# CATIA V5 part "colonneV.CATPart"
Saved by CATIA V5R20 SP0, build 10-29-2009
Part number: colonneV
Bounding box of the stored display mesh (mm): x -50 to 50, y -150 to 249.996, z 40 to 1049.996
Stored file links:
  D:\Dropbox\Pack 1 sylvain\mmoreau\mmoreau\mmoreau\fin\colonneV.CATPart
  U:\think motion\fin\think motion2.CATProduct
  D:\Dropbox\Pack 1 sylvain\mmoreau\mmoreau\mmoreau\fin\verinB1.CATPart
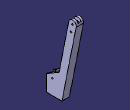
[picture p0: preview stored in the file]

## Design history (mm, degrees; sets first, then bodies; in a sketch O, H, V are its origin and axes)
External parameters (linked from other documents)
  `External.largeur levier` = 40 mm
  `External.décalage base` = 40 mm
Set1
  Line1: linked copy from another document
  Point1 to Point3: linked copy from another document
  Line2: linked copy from another document
  Point4: linked copy from another document
Body1 (main body)
  Sketch1 on yz-plane, origin (0, 0, 0), H (0, 1, 0), V (0, 0, 1)
    line L1 (249.029, 990.1942) -> (58.9902, 40)
    reference projected line E1 (200, 1000) -> (0, 0) from Line1
    line L2 (150.971, 1009.8058) -> (19.5927, 352.9144)
    line L3 (19.5927, 352.9144) -> (-150, 255)
    line L4 (58.9902, 40) -> (-150, 40)
    line L5 (-150, 255) -> (-150, 40)
    reference projected line E2 (200, 1000) -> (0, 0) from Line1
    arc A1 centre (200, 1000) radius 50 from (249.029, 990.1942) to (150.971, 1009.8058) ccw
    point P5 (200, 1000)
    reference projected point E3 (200, 1000) from Point1
    circle A2 centre (200, 1000) radius 10
    point P8 (200, 1000)
    circle A3 centre (180.3884, 901.9419) radius 10
    point P9 (180.3884, 901.9419)
    reference projected point E4 (200, 1000) from Point1
    reference projected point E5 (180.3884, 901.9419) from Point2
    distance L1 L2 = 100
    radius A2 = 10
    radius A3 = 10
    distance H L4 = 40 {= `External.décalage base`}
    angle L3 L5 = 120
    length L5 = 215
    distance L5 V = 150
    parallelism: L1 E1
    horizontal: L4 H
    vertical: L5 V
    symmetry: L1 L2 E2
    coincidence: E3 P5, P8 E4, P9 E5
    tangency: A1 L2
  Pad1: profile Sketch1, direction (1, 0, 0), length 50 {= `External.largeur levier` +10mm}, mirrored extent
  Sketch2 on yz-plane, origin (0, 0, 0), H (0, 1, 0), V (0, 0, 1)
    line L1 (261.2594, 1102.3364) -> (196.0777, 776.4276)
    line L2 (196.0777, 776.4276) -> (-62.07, 828.0571)
    line L3 (-62.07, 828.0571) -> (3.1118, 1153.966)
    line L4 (3.1118, 1153.966) -> (261.2594, 1102.3364)
    reference projected line E1 (200, 1000) -> (0, 0) from Line1
    reference projected line E2 (200, 1000) -> (0, 0) from Line1
    reference projected point E3 (180.3884, 901.9419) from Point2
    distance L1 E2 = 40
    distance L2 E3 = 120
    parallelism: L4 L2, L1 L3, E1 L1
    perpendicularity: L1 L2
  Pocket1: profile Sketch2, direction (-1, 0, 0), length 20 {= `External.largeur levier` /2}, mirrored extent
  Sketch3 on yz-plane, origin (0, 0, 0), H (0, 1, 0), V (0, 0, 1)
    circle A1 centre (-70, 240) radius 10
    point P1 (-70, 240)
    reference projected point E1 (-70, 240) from Point3
    radius A1 = 10
    coincidence: E1 P1
  Pocket2: profile Sketch3, direction (-1, 0, 0), length 91, mirrored extent
  Sketch4 on yz-plane, origin (0, 0, 0), H (0, 1, 0), V (0, 0, 1)
    line L1 (9.3216, 455.998) -> (-27.5765, 180)
    line L2 (-27.5765, 180) -> (-194.0445, 180)
    line L3 (-194.0445, 180) -> (-154.2234, 477.8623)
    line L4 (-154.2234, 477.8623) -> (9.3216, 455.998)
    reference projected line E1 (-3.1227, 740.2423) -> (-69.3781, 244.6515) from Line2
    reference projected line E2 (-3.1227, 740.2423) -> (-69.3781, 244.6515) from Line2
    reference projected point E3 (-70, 240) from Point4
    reference projected line E4 (-150, 40) -> (58.9902, 40) from edge [face of Pad1 from Sketch1.L4 | end face of Pad1]
    distance L1 L3 = 165
    distance L1 E2 = 50
    distance L2 E3 = 60
    parallelism: E1 L1, E4 L2
  Pocket3: profile Sketch4, direction (-1, 0, 0), length 20, mirrored extent
  Sketch5 on xy-plane, origin (0, 0, 0), H (1, 0, 0), V (0, 1, 0)
    line L1 (0.525, -94.494) -> (-0.525, -94.494)
    point P1 (28, -94.494)
    line L2 (34.524, -121.1831) -> (50, -184.494)
    point P2 (50, -184.494)
    reference projected point E1 (0, -69.494)
    point P3 (-50, -184.494)
    point P4 (-28, -94.494)
    line L3 (-34.524, -121.1831) -> (-50, -184.494)
    arc A1 centre (0.525, -129.494) radius 35 from (34.524, -121.1831) to (0.525, -94.494) ccw
    arc A2 centre (-0.525, -129.494) radius 35 from (-34.524, -121.1831) to (-0.525, -94.494) cw
    line L4 (50, -184.494) -> (-50, -184.494)
    point P11 (-50, -184.494)
    distance L1 E1 = 25
    distance P1 V = 28
    distance P2 V = 50
    distance P2 L1 = 90
    radius A1 = 35
    radius A2 = 35
    horizontal: L1 H
    symmetry: P2 P3 V, P1 P4 V, L2 L3 V
    coincidence: L2 P1, L1 P1, L3 P4, L1 P4, P3 P11
    tangency: A1 L2, A1 L1, A2 L3, A2 L1
  Pocket4: profile Sketch5, direction (0, 0, 1), length 400, opposite side length -180
  Fillet1: radius 5, on edge [face of Pocket4 from Sketch5.A1 | start face of Pocket3]; edge [end face of Pocket3 | face of Pocket4 from Sketch5.A2]; edge [face of Pad1 from Sketch1.L5 | face of Pocket4 from Sketch5.L3]; edge [face of Pocket4 from Sketch5.L2 | face of Pad1 from Sketch1.L5]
